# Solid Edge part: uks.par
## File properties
Author: Administrator
Template: Normal.par
Last saved by: Administrator
Revision: 2
Application: Solid Edge
Accuracy: 0,990
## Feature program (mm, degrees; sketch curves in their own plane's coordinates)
sketch for "unnamed Protrusion 1" plane through (0, 0, 0) normal (1, 0, 0) x-axis (0, 1, 0)
  line (-25, 74.375) -> (25, 74.375)
  line (25, 74.375) -> (25, -74.375)
  line (25, -74.375) -> (-25, -74.375)
  line (-25, -74.375) -> (-25, 74.375)
extrude "unnamed Protrusion 1" add finite 2.5 symmetric
sketch for "ExtrudedCutout_1" #1 plane through (1.25, 0, 0) normal (1, 0, 0) x-axis (0, 1, 0)
  line (-15, -64.375) -> (-15, 64.375)
  line (-15, 64.375) -> (15, 64.375)
  line (15, 64.375) -> (15, -64.375)
  line (15, -64.375) -> (-15, -64.375)
sketch for "ExtrudedCutout_1" #2 plane through (1.25, 0, 0) normal (1, 0, 0) x-axis (0, 1, 0)
  line (-10, -59.375) -> (-10, 59.375)
  line (-10, 59.375) -> (10, 59.375)
  line (10, 59.375) -> (10, -59.375)
  line (10, -59.375) -> (-10, -59.375)
extrude "ExtrudedCutout_1" cut finite 1 along -normal
sketch for "ExtrudedProtrusion_2" plane through (1.25, 0, 0) normal (1, 0, 0) x-axis (0, 1, 0)
  circle centre (-20, 0) radius 1.5
extrude "ExtrudedProtrusion_2" add finite 7.5 along +normal
sketch for "ExtrudedProtrusion_3" plane through (8.75, -20, 0) normal (1, 0, 0) x-axis (0, 1, 0)
  line (0, 1.5) -> (13.6, 1.5)
  arc centre (13.6, 0.1) radius 1.4 from (13.6, 1.5) to (15, 0.1) cw
  line (15, 0.1) -> (15, -0.1)
  arc centre (13.6, -0.1) radius 1.4 from (13.6, -1.5) to (15, -0.1) ccw
  line (0, -1.5) -> (13.6, -1.5)
extrude "ExtrudedProtrusion_3" add finite 1.25 along +normal
fillet "Round_1" radius 0.5
mirror "unnamed Mirror 1" of "Round_1", "ExtrudedProtrusion_3", "ExtrudedProtrusion_2" about plane through (0, 0, 0) normal (1, 0, 0)
extrude "unnamed Protrusion 2" add finite 7.5
extrude "unnamed Protrusion 3" add finite 1.25
fillet "unnamed Round 1"
fillet "Round_4" radius 1
mirror "unnamed Mirror 2" of "Round_4", "ExtrudedCutout_1" about plane through (0, 0, 0) normal (1, 0, 0)
extrude "unnamed Cutout 1" cut finite 1
fillet "unnamed Round 2"
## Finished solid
Body 1: solid body, 66 faces, 146 edges, 88 vertices.
  Faces by surface: cylinder 34, plane 20, torus 12
  Edges by curve: line 80, circle 46, ellipse 16, intersection 4
Bounding box of the edges (mm; curved faces can reach further): 20.000 x 50.000 x 148.750, from (-10, -25, -74.375) to (10, 25, 74.375).
Cylindrical faces by radius (mm): R0.5 x12, R1 x16, R1.4 x4, R1.5 x2
Toroidal faces (ring radius, tube radius in mm): R0.9 r0.5 x8, R1 r0.5 x2, R2 r0.5 x2
Planar faces by outward normal: +x 5, +y 3, +z 3, -x 5, -y 1, -z 3
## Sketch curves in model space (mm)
arc centre (8.75, -6.4, -0.1) radius 1.4 from (8.75, -6.4, -1.5) through (8.75, -5.3817, -1.0607) to (8.75, -5, -0.1)
line (8.75, -20, -1.5) -> (8.75, -6.4, -1.5)
arc centre (8.75, -20, 0) radius 1.5 from (8.75, -20, -1.5) through (8.75, -21.4993, 0.0444) to (8.75, -20, 1.5)
line (8.75, -20, 1.5) -> (8.75, -6.4, 1.5)
arc centre (8.75, -6.4, 0.1) radius 1.4 from (8.75, -6.4, 1.5) through (8.75, -5.3817, 1.0607) to (8.75, -5, 0.1)
line (8.75, -5, 0.1) -> (8.75, -5, -0.1)
circle centre (1.25, -20, 0) radius 1.5
line (1.25, -35.4029, 0) -> (1.25, 34.6388, 0)
line (1.25, -20, 3.2095) -> (1.25, -20, -8.8064)
line (1.25, -15, 64.375) -> (1.25, 15, 64.375)
line (1.25, 15, 64.375) -> (1.25, 15, -64.375)
line (1.25, 15, -64.375) -> (1.25, -15, -64.375)
line (1.25, -15, -64.375) -> (1.25, -15, 64.375)
line (1.25, -10, 59.375) -> (1.25, 10, 59.375)
line (1.25, 10, 59.375) -> (1.25, 10, -59.375)
line (1.25, 10, -59.375) -> (1.25, -10, -59.375)
line (1.25, -10, -59.375) -> (1.25, -10, 59.375)
line (0, 25, 74.375) -> (0, 25, -74.375)
line (0, 25, -74.375) -> (0, -25, -74.375)
line (0, -25, -74.375) -> (0, -25, 74.375)
line (0, -25, 74.375) -> (0, 25, 74.375)
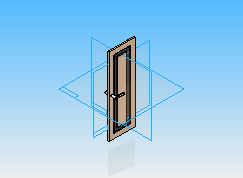
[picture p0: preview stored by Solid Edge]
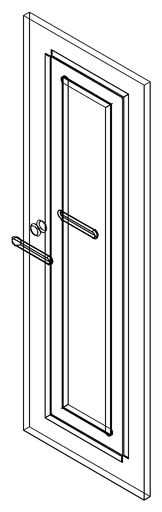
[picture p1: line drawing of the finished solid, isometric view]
